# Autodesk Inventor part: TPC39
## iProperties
Shininess: 64.0
Length Units: 11272
Angle Units: 11279
Time Units: 11290
Mass Units: 11286
Length Display Precision: 3
Angle Display Precision: 2
Compacted: True
Part Number: TPC39
Document SubType Name: Modeling
Created: 2004-08
Designer: Lori
Manufacturer: Standard
Standards Organization: Custom
Material: Aluminum-6061
Density: 0.0
Volumn: 0.0
Area: 0.0
PropertySet Name: Model Information
Control State: 0
Master: False
Checked Out: False
Author: Lori
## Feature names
1. Base1
